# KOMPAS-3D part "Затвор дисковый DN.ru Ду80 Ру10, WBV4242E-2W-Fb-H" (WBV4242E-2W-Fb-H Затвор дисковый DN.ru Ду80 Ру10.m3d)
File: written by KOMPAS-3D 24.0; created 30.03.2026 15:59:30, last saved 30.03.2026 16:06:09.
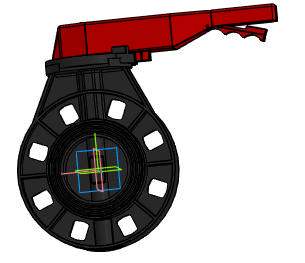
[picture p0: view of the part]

Document properties: Автор: R2D2; Полное имя файла: E:\Работа\Зайцев\WBV4242E-2W-Fb-H Затвор дисковый DN.ru Ду50-200 Ру10\DN80\WBV4242E-2W-Fb-H Затвор дисковый DN.ru Ду80 Ру10.m3d

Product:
- Part/product: Затвор дисковый DN.ru Ду80 Ру10  | designation WBV4242E-2W-Fb-H
    Масса: 1.8
    Раздел спецификации: Прочие изделия
    Примечание: D050-81199

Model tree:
1. Операция без истории:1

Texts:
  WBV4242E-2W-Fb-H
